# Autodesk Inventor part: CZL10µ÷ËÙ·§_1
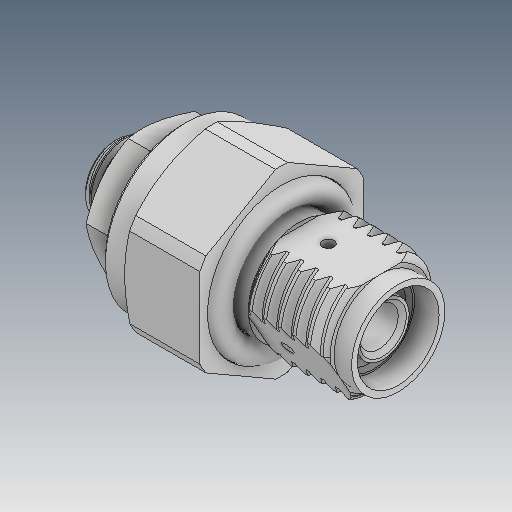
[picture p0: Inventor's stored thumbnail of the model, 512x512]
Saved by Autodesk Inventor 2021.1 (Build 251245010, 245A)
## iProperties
Created: 2019-04
Part Number: CZL10µ÷ËÙ·§_1
Material: Ogólny
Document SubType Name: Modeling
Designer: user
Density: 1 g/cm^3
Appearance: Domyślna
Author: user
Revision Number: ÈÎºÎ
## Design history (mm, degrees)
feature "ÊäÈë1"
feature "ÊäÈë3"
feature "ÊäÈë5"
node "Bryła1"
node "Bryła2"
node "Bryła3"
